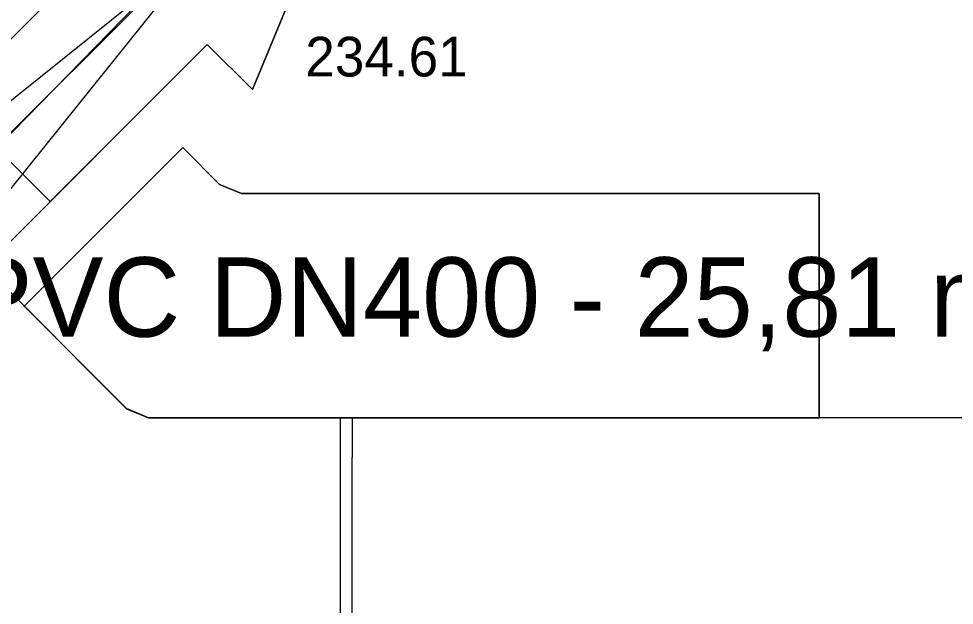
# Model space of a CAD drawing. Extents: x -264234 to -263604, y -1242346 to -1242049.
# Drawn here: x -263895.14 to -263871.58, y -1242239.48 to -1242224.7 of the extents above; entities that cross this region are included whole.
import ezdxf

# ---------------------------------------------------------------- set-up
doc = ezdxf.new("R2010")
doc.units = 0
for name, color, linetype in [('KFA_BODY_VYSKA', 7, 'Continuous'), ('KFA_DAZDOVA_KANALIZACIA_vetva_I', 7, 'Continuous'), ('KFA_DAZDOVA_KANALIZACIA_vetva_I_popis', 7, 'Continuous'), ('KFA_SITUACIA_DSP', 7, 'Continuous')]:
    doc.layers.add(name, color=color, linetype=linetype)

msp = doc.modelspace()

# ---------------------------------------------------------------- linework, layer by layer
at = {"layer": 'KFA_DAZDOVA_KANALIZACIA_vetva_I'}
msp.add_lwpolyline([(-263814.907, -1242107.856), (-263815.198, -1242164.443), (-263815.189, -1242220.791), (-263852.152, -1242220.736), (-263888.701, -1242220.786), (-263906.731, -1242239.259)], dxfattribs=at)
at = {"layer": 'KFA_SITUACIA_DSP'}
for p, q in [((-263889.023, -1242221.253), (-263906.365, -1242238.596)), ((-263895.005, -1242231.945), (-263891.01, -1242227.95)), ((-263891.01, -1242227.95), (-263890.082, -1242228.878)), ((-263890.082, -1242228.878), (-263889.528, -1242229.107)), ((-263889.528, -1242229.107), (-263874.98, -1242229.107)), ((-263874.98, -1242229.107), (-263874.98, -1242234.757)), ((-263892.422, -1242234.528), (-263895.005, -1242231.945)), ((-263891.868, -1242234.757), (-263892.422, -1242234.528)), ((-263874.98, -1242234.757), (-263891.868, -1242234.757)), ((-263887.043, -1242234.757), (-263887.043, -1242235.757)), ((-263886.743, -1242234.757), (-263886.743, -1242235.757)), ((-263887.043, -1242235.757), (-263887.043, -1242250.954)), ((-263886.743, -1242249.39), (-263886.743, -1242235.757))]:
    msp.add_line(p, q, dxfattribs=at)
for points in [[(-263811.918, -1242108.434), (-263811.918, -1242220.33), (-263812.262, -1242220.675), (-263809.862, -1242221.669), (-263810.999, -1242222.806), (-263807.039, -1242226.765), (-263809.585, -1242229.311), (-263813.545, -1242225.351), (-263814.681, -1242226.488), (-263815.675, -1242224.088), (-263816.02, -1242224.432), (-263887.916, -1242224.432), (-263888.26, -1242224.088), (-263889.254, -1242226.488), (-263890.391, -1242225.351), (-263894.351, -1242229.311), (-263896.896, -1242226.765), (-263892.937, -1242222.806), (-263894.073, -1242221.669), (-263891.673, -1242220.675), (-263892.018, -1242220.33), (-263892.018, -1242181.432), (-263893.618, -1242181.432), (-263893.618, -1242147.332)], [(-263891.673, -1242220.675), (-263894.073, -1242221.669), (-263892.937, -1242222.806), (-263898.544, -1242228.407)], [(-263895.995, -1242230.956), (-263890.391, -1242225.352), (-263889.254, -1242226.488), (-263888.26, -1242224.088), (-263891.673, -1242220.675)], [(-263903.277, -1242233.148), (-263900.731, -1242235.694), (-263890.333, -1242222.748), (-263903.277, -1242233.148)], [(-263807.942, -1242230.956), (-263811.512, -1242234.526), (-263812.068, -1242234.757), (-263891.868, -1242234.757), (-263892.424, -1242234.526), (-263895.994, -1242230.956)]]:
    msp.add_lwpolyline(points, dxfattribs=at)
msp.add_lwpolyline([(-263891.01, -1242227.95), (-263895.005, -1242231.945), (-263892.422, -1242234.528), (-263891.868, -1242234.757), (-263874.98, -1242234.757), (-263874.98, -1242229.107), (-263889.528, -1242229.107), (-263890.082, -1242228.878)], close=True, dxfattribs=at)

# ---------------------------------------------------------------- texts
at = {"layer": 'KFA_BODY_VYSKA'}
msp.add_text('234.61', height=1, dxfattribs=at).set_placement((-263887.923, -1242226.158))
at = {"layer": 'KFA_DAZDOVA_KANALIZACIA_vetva_I_popis'}
msp.add_text('PVC DN400 - 25,81 m', height=2, dxfattribs=at).set_placement((-263896.573, -1242232.714))

doc.saveas('drawing.dxf')
